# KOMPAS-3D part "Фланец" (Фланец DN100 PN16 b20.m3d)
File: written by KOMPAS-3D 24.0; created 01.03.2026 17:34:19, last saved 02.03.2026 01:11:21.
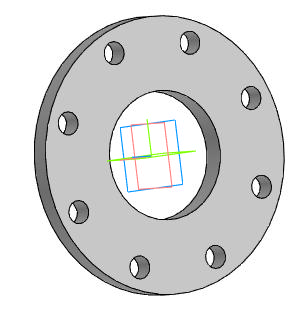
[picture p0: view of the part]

Document properties: Автор: R2D2; Полное имя файла: E:\Работа\Зайцев\GVWR2626M-2W-F-S Задвижка клиновая с выдвижным штоком DN.ru Ду50-300 Ру16\DN100\исходные материалы\Фланец DN100 PN16 b20.m3d

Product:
- Part/product: Фланец
    Масса: 3.822467
    additional columns: Типовые

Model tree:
1. Эскиз:2
2. Элемент вращения:1
     Угол 1 = 360
3. Эскиз:3  (with: Грань.Элемент вращения:1)
4. Элемент выдавливания:2
     Расстояние 1 = 50
5. Массив по концентрической сетке:1  (with: Элемент выдавливания:2, Эскиз:3, Грань.Элемент вращения:1)  (8 pattern instances)
     Шаг 2 = 360
6. Эскиз:4  (with: Грань.Элемент вращения:1)
7. Элемент выдавливания:3
     Расстояние 2 = 3

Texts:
  Линейный размер с обрывом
